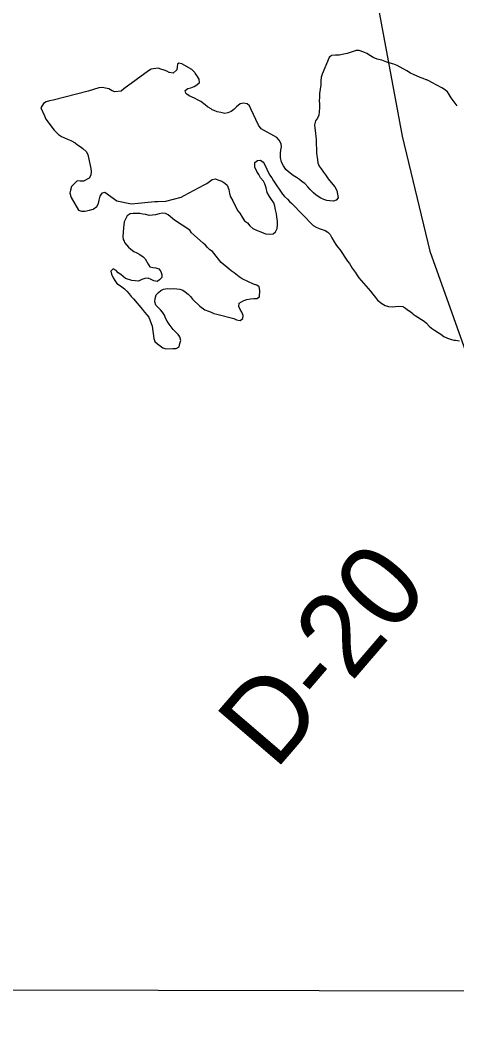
# Model space of a CAD drawing. Extents: x 3172231 to 3210228, y 940198 to 965780.
# Drawn here: x 3191660 to 3192098, y 945652 to 946666 of the extents above; entities that cross this region are included whole.
import ezdxf

# ---------------------------------------------------------------- set-up
doc = ezdxf.new("R2010")
doc.units = 0
for name, color, linetype in [('V-GRID-FRAM', 7, 'Continuous'), ('V-RIVR-RANG-IDEN', 7, 'Continuous'), ('V-TOPO-MAJR', 7, 'Continuous'), ('V-TOPO-SHOR', 7, 'Continuous')]:
    doc.layers.add(name, color=color, linetype=linetype)

msp = doc.modelspace()

# ---------------------------------------------------------------- linework, layer by layer
at = {"layer": 'V-GRID-FRAM'}
msp.add_lwpolyline([(3176539.592, 963919.479), (3207827.662, 963842.116), (3207790.623, 945652.442), (3176486.679, 945729.845), (3176539.592, 963919.479)], dxfattribs=at)
at = {"layer": 'V-TOPO-MAJR'}
msp.add_lwpolyline([(3191965.03, 946881.133), (3192003.878, 946837.926), (3192011.775, 946806.095), (3192015.704, 946778.248), (3192015.631, 946734.499), (3192017.539, 946686.769), (3192043.148, 946549.513), (3192070.782, 946434.128), (3192118.261, 946300.812), (3192181.541, 946107.812), (3192282.525, 945878.955), (3192347.711, 945691.839)], dxfattribs=at)
at = {"layer": 'V-TOPO-SHOR'}
msp.add_line((3191895.457, 946518.472), (3191895.254, 946519.469), dxfattribs=at)
for points in [[(3192098.127, 946579.822), (3192096.37, 946582.703), (3192094.201, 946585.392), (3192092.235, 946588.075), (3192090.285, 946591.367), (3192088.516, 946593.843), (3192085.528, 946596.144), (3192082.935, 946598.033), (3192072.916, 946603.339), (3192069.907, 946604.83), (3192067.7, 946605.897), (3192067.096, 946606.114), (3192064.282, 946607.193), (3192061.06, 946608.283), (3192054.441, 946611.484), (3192051.424, 946612.567), (3192047.623, 946614.89), (3192041.221, 946618.693), (3192038.016, 946620.391), (3192034.596, 946621.687), (3192030.971, 946622.787), (3192027.547, 946623.883), (3192022.517, 946625.623), (3192018.079, 946626.742), (3192014.063, 946628.46), (3192011.261, 946630.147), (3192007.658, 946632.261), (3192004.652, 946633.752), (3192000.021, 946635.282), (3191996.777, 946635.358), (3191993.914, 946634.409), (3191991.051, 946633.463), (3191987.785, 946632.525), (3191984.723, 946631.786), (3191980.035, 946630.883), (3191976.179, 946630.77), (3191972.312, 946630.252), (3191969.836, 946628.484), (3191962.947, 946611.605), (3191961.865, 946608.791), (3191961.572, 946604.943), (3191961.482, 946601.088), (3191960.264, 946592.395), (3191960.174, 946588.542), (3191959.885, 946584.897), (3191960.016, 946581.849), (3191960.128, 946577.993), (3191959.825, 946573.739), (3191959.342, 946570.506), (3191958.056, 946567.493), (3191956.164, 946564.695), (3191955.056, 946560.665), (3191955.383, 946557.411), (3191956.075, 946552.323), (3191956.938, 946545.811), (3191957.028, 946532.419), (3191958.089, 946525.699), (3191958.422, 946522.648), (3191959.963, 946519.162), (3191961.73, 946516.686), (3191964.286, 946513.178), (3191966.053, 946510.702), (3191969.004, 946506.778), (3191971.757, 946503.061), (3191975.509, 946498.713), (3191977.446, 946494.812), (3191978.177, 946491.346), (3191978.896, 946487.474), (3191977.014, 946485.084)], [(3191901.644, 946556.944), (3191898.887, 946560.456), (3191891.158, 946576.869), (3191890.007, 946579.736), (3191887.627, 946582.024), (3191883.992, 946582.718), (3191880.525, 946581.987), (3191877.002, 946578.825), (3191874.299, 946576.047), (3191871.413, 946574.085), (3191868.14, 946572.947), (3191865.079, 946572.205), (3191861.042, 946573.113), (3191857.616, 946574.006), (3191854.601, 946575.294), (3191852.385, 946575.953), (3191851.595, 946576.783), (3191847.79, 946578.902), (3191845.4, 946580.784), (3191841.217, 946584.129), (3191838.412, 946585.614), (3191834.607, 946587.731), (3191829.585, 946589.88), (3191826.988, 946591.563), (3191825.999, 946592.601), (3191825.452, 946595.252), (3191828.141, 946597.418), (3191831.195, 946597.957), (3191834.473, 946599.298), (3191837.146, 946600.859), (3191839.636, 946603.237), (3191839.309, 946606.489), (3191836.966, 946610.399), (3191835.6, 946612.664), (3191835.01, 946613.489), (3191832.03, 946616.196), (3191822.026, 946622.111), (3191818.993, 946622.588), (3191817.758, 946621.806), (3191817.285, 946618.978), (3191817.215, 946615.934), (3191813.281, 946612.58), (3191809.846, 946613.268), (3191809.447, 946613.481), (3191807.036, 946614.552), (3191804.222, 946615.631), (3191801.003, 946616.723), (3191798.187, 946617.802), (3191791.467, 946616.743), (3191790.433, 946615.957), (3191788.586, 946614.984), (3191764.022, 946597.101), (3191761.126, 946594.733), (3191755.019, 946593.863), (3191752.205, 946594.944), (3191749.004, 946596.845), (3191745.572, 946597.533), (3191742.545, 946598.215), (3191738.682, 946597.9), (3191728.26, 946594.695), (3191693.151, 946585.579), (3191689.285, 946585.061), (3191686.012, 946583.92), (3191683.337, 946582.361), (3191680.597, 946577.962)], [(3191680.597, 946577.962), (3191684.462, 946569.756), (3191685.805, 946566.477), (3191693.86, 946555.334), (3191696.246, 946553.249), (3191698.22, 946550.972), (3191701.22, 946549.073), (3191704.436, 946547.781), (3191707.246, 946546.499), (3191710.862, 946544.994), (3191715.069, 946542.663), (3191717.459, 946540.781), (3191720.056, 946539.095), (3191722.851, 946537.205), (3191726.226, 946534.082), (3191727.779, 946531.004), (3191729.251, 946524.68), (3191730.693, 946516.936), (3191731.23, 946513.88), (3191730.742, 946510.442), (3191729.051, 946507.439), (3191723.498, 946504.322), (3191720.254, 946504.4), (3191717.213, 946504.472), (3191714.729, 946502.299), (3191711.403, 946498.928), (3191710.303, 946495.301), (3191709.822, 946492.065), (3191710.942, 946487.983), (3191718.352, 946475.231), (3191721.371, 946474.145), (3191724.817, 946474.063), (3191729.307, 946475.175), (3191733.188, 946476.302), (3191736.696, 946478.858), (3191738.389, 946481.86), (3191739.08, 946485.292), (3191740.188, 946489.325), (3191742.084, 946492.323), (3191742.293, 946492.522), (3191744.947, 946493.269), (3191756.787, 946484.528), (3191771.663, 946481.463), (3191794.834, 946483.779), (3191797.882, 946483.91), (3191806.006, 946484.328), (3191821.516, 946488.223), (3191824.393, 946489.78), (3191844.328, 946500.673), (3191847.2, 946502.025), (3191849.682, 946503.997), (3191852.365, 946505.961), (3191855.42, 946506.497), (3191859.045, 946505.398), (3191862.06, 946504.109), (3191865.261, 946502.209), (3191867.651, 946500.327), (3191869.169, 946495.827), (3191869.883, 946491.754), (3191871.024, 946488.481), (3191873.367, 946484.572), (3191874.715, 946481.495), (3191876.453, 946477.805), (3191878.01, 946474.927), (3191880.172, 946472.036), (3191882.718, 946468.122), (3191885.065, 946464.413), (3191888.059, 946462.316), (3191890.427, 946459.42), (3191893.411, 946456.915), (3191897.621, 946454.787), (3191901.242, 946453.485), (3191905.863, 946451.55), (3191909.504, 946451.058), (3191913.567, 946451.369), (3191916.053, 946453.542), (3191917.548, 946456.754), (3191918.04, 946460.393), (3191918.116, 946463.639), (3191917.415, 946468.321), (3191916.883, 946471.579), (3191915.963, 946475.659), (3191915.234, 946479.124), (3191914.3, 946482.595), (3191912.148, 946485.892), (3191909.987, 946488.987), (3191907.646, 946492.895), (3191906.741, 946497.582), (3191905.209, 946501.474), (3191903.858, 946504.345), (3191901.095, 946507.657), (3191899.143, 946510.948), (3191897.386, 946513.829), (3191895.457, 946518.472)], [(3191977.014, 946485.084), (3191974.151, 946484.137), (3191970.508, 946484.426), (3191967.471, 946484.701), (3191964.454, 946485.786), (3191961.439, 946487.072), (3191956.848, 946490.224), (3191954.062, 946492.522), (3191950.894, 946495.842), (3191948.32, 946498.541), (3191945.557, 946501.85), (3191942.761, 946503.743), (3191940.179, 946506.035), (3191936.978, 946507.935), (3191933.576, 946510.045), (3191928.999, 946513.805), (3191926.41, 946515.894), (3191924.063, 946519.6), (3191922.122, 946523.297), (3191921.02, 946528.194), (3191920.911, 946532.253), (3191921.395, 946535.489), (3191921.876, 946538.723), (3191921.745, 946541.768), (3191919.803, 946545.467), (3191917.225, 946547.961), (3191901.644, 946556.944)], [(3191895.254, 946519.469), (3191895.354, 946522.877), (3191898.017, 946524.878), (3191901.072, 946525.417), (3191903.661, 946523.326), (3191904.642, 946521.884), (3191909.854, 946510.602), (3191912.216, 946507.503), (3191914.175, 946504.617), (3191923.195, 946491.217), (3191924.962, 946488.741), (3191927.946, 946486.237), (3191930.123, 946483.955), (3191932.509, 946481.87), (3191953.7, 946459.866), (3191956.903, 946457.966), (3191959.717, 946456.885), (3191965.756, 946454.916), (3191968.552, 946453.026), (3191970.934, 946450.739), (3191972.677, 946447.249), (3191974.817, 946443.343), (3191976.584, 946440.867), (3191978.352, 946438.391), (3191980.52, 946435.702), (3191988.36, 946423.955), (3191990.128, 946421.479), (3191993.064, 946416.947), (3191995.813, 946413.027), (3191997.57, 946410.145), (3191999.532, 946407.26), (3192011.392, 946393.997), (3192013.546, 946390.699), (3192016.313, 946387.591), (3192018.476, 946384.701), (3192022.664, 946381.557), (3192026.064, 946379.45), (3192029.486, 946378.354), (3192032.935, 946378.274), (3192036.386, 946378.395), (3192039.847, 946378.923), (3192043.691, 946378.428), (3192044.492, 946378.002), (3192046.288, 946376.742), (3192046.892, 946376.525), (3192049.479, 946374.436), (3192049.681, 946374.43), (3192053.671, 946371.497), (3192054.265, 946370.875), (3192056.26, 946369.408), (3192065.052, 946363.723), (3192067.438, 946361.638), (3192070.211, 946358.732), (3192072.601, 946356.85), (3192075.589, 946354.548), (3192079.187, 946352.234), (3192081.784, 946350.548), (3192084.981, 946348.445), (3192088.587, 946346.534), (3192092.417, 946345.43), (3192094.836, 946344.765), (3192096.66, 946344.722), (3192100.498, 946344.023)], [(3191857.3, 946370.729), (3191874.237, 946366.273), (3191877.053, 946365.194), (3191880.482, 946364.301), (3191883.165, 946366.267), (3191883.439, 946369.304), (3191882.102, 946372.783), (3191880.541, 946375.458), (3191879.394, 946378.528), (3191879.472, 946381.772), (3191884.406, 946384.496), (3191887.273, 946385.647), (3191890.937, 946386.169), (3191894.189, 946386.499), (3191897.236, 946386.63), (3191899.909, 946388.191), (3191900.265, 946394.672), (3191899.534, 946398.14), (3191897.144, 946400.022), (3191893.921, 946400.909), (3191882.481, 946406.25), (3191879.685, 946408.14), (3191874.504, 946412.117), (3191871.509, 946414.217), (3191869.328, 946416.297), (3191861.562, 946422.564), (3191852.893, 946433.521), (3191850.098, 946435.413), (3191847.921, 946437.697), (3191845.742, 946439.978), (3191843.356, 946442.063), (3191831.834, 946452.477), (3191830.066, 946454.953), (3191814.688, 946465.257), (3191808.519, 946470.473), (3191805.709, 946471.757), (3191802.471, 946472.036), (3191799.213, 946471.503), (3191795.738, 946470.369), (3191792.686, 946470.035), (3191789.233, 946469.914), (3191786.01, 946470.801), (3191782.976, 946471.278), (3191779.945, 946471.753), (3191776.499, 946471.835), (3191773.255, 946471.911), (3191770.199, 946471.374), (3191767.109, 946469.418), (3191765.411, 946466.211), (3191764.127, 946463.401), (3191763.584, 946457.532)], [(3191763.584, 946457.532), (3191762.968, 946448.619), (3191763.301, 946445.567), (3191764.075, 946443.927), (3191764.452, 946442.7), (3191766.422, 946440.22), (3191768.602, 946437.936), (3191770.992, 946436.054), (3191773.98, 946433.752), (3191776.785, 946432.268), (3191779.99, 946430.57), (3191783.183, 946428.262), (3191785.366, 946426.183), (3191788.285, 946420.84), (3191790.046, 946418.161), (3191793.073, 946417.479), (3191796.114, 946417.409), (3191798.924, 946416.125), (3191800.89, 946413.442), (3191802.041, 946410.573), (3191801.97, 946407.534), (3191799.895, 946405.554), (3191799.686, 946405.355), (3191797.21, 946403.587), (3191793.976, 946404.069), (3191791.171, 946405.556), (3191788.158, 946406.844), (3191785.106, 946406.51), (3191781.838, 946405.572), (3191778.76, 946404.022), (3191775.108, 946404.108), (3191772.077, 946404.585), (3191765.632, 946406.561), (3191763.246, 946408.646), (3191760.86, 946410.731), (3191758.263, 946412.414), (3191756.084, 946414.698), (3191753.278, 946416.185), (3191750.794, 946414.01), (3191751.534, 946410.95), (3191753.272, 946407.257), (3191754.833, 946404.583), (3191756.996, 946401.691), (3191759.388, 946399.811), (3191761.984, 946398.125), (3191764.573, 946396.036), (3191766.953, 946393.749), (3191769.128, 946391.263), (3191771.295, 946388.576), (3191773.67, 946386.083), (3191782.755, 946375.524), (3191784.519, 946372.845), (3191786.89, 946370.152), (3191788.864, 946367.874), (3191792.305, 946358.867), (3191793.835, 946346.252), (3191794.984, 946343.384), (3191797.562, 946340.89), (3191800.36, 946338.998), (3191802.953, 946337.111), (3191806.172, 946336.022), (3191813.08, 946336.468), (3191816.529, 946336.386), (3191819.408, 946338.146), (3191820.088, 946341.173), (3191821.18, 946344.392), (3191820.043, 946347.868), (3191818.276, 946350.344), (3191815.701, 946353.043), (3191813.326, 946355.531), (3191811.356, 946358.013), (3191809.394, 946360.899), (3191807.434, 946363.787), (3191805.681, 946366.871), (3191804.53, 946369.738), (3191802.574, 946372.826), (3191800.6, 946375.106), (3191798.224, 946377.594), (3191796.045, 946379.878), (3191795.107, 946383.146), (3191795.183, 946386.39), (3191796.288, 946390.218), (3191798.572, 946392.397), (3191800.849, 946394.371), (3191803.721, 946395.725), (3191807.598, 946396.649), (3191810.629, 946396.172), (3191813.883, 946396.499), (3191817.123, 946396.221), (3191820.16, 946395.946), (3191822.974, 946394.867), (3191825.573, 946393.184), (3191828.358, 946390.886), (3191830.734, 946388.395), (3191832.907, 946385.909), (3191840.044, 946378.844), (3191845.029, 946375.075), (3191848.65, 946373.773), (3191851.464, 946372.691), (3191854.273, 946371.409), (3191857.3, 946370.729)]]:
    msp.add_lwpolyline(points, dxfattribs=at)

# ---------------------------------------------------------------- texts
at = {"layer": 'V-RIVR-RANG-IDEN'}
msp.add_text('D-20', height=83, rotation=49.403266, dxfattribs=at).set_placement((3191915.65, 945911.743))

doc.saveas('drawing.dxf')
